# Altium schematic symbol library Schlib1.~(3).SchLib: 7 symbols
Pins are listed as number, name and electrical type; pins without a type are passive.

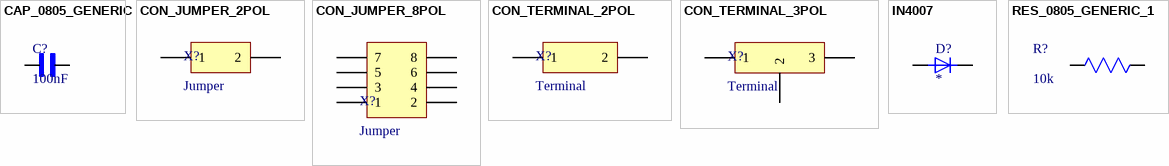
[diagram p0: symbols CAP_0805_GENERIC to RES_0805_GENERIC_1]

## CAP_0805_GENERIC
designator C?, comment 100nF
0.1 ÂµF Â±10% 50V Ceramic Capacitor X7R 0805 (2012 Metric); MF: Samsung Electro-Mechanics; MP: CL21B104KBCNNNC
footprint CAPC2012X95N
pins: 1, 2

## CON_JUMPER_2POL
designator X?, comment Jumper
Manufacturer_Name: Yageo; Manufacturer_Part_Number: RC0805FR-0710KL; Value: 10k
footprint CON_JUMPER_2POL (Jumper)
pins: 1, 2

## CON_JUMPER_8POL
designator X?, comment Jumper
Manufacturer_Name: Yageo; Manufacturer_Part_Number: RC0805FR-0710KL; Value: 10k
footprint CON_JUMPER_8POL (Jumper)
pins: 1, 2, 3, 4, 5, 6, 7, 8

## CON_TERMINAL_2POL
designator X?, comment Terminal
Terminal Screw; Manufacturer_Name: Yageo; Manufacturer_Part_Number: RC0805FR-0710KL; Value: 10k
footprint CON_TERMINAL_2POL (Terminal Screw)
pins: 1, 2

## CON_TERMINAL_3POL
designator X?, comment Terminal
Terminal block; Manufacturer_Name: Yageo; Manufacturer_Part_Number: RC0805FR-0710KL; Value: 10k
footprint CON_TERMINAL_3POL (Terminal Screw)
pins: 1, 2, 3

## IN4007
designator D?
Diode Standard 1000 V 1A Through Hole DO-204AL (DO-41); MF: Vishay Semiconductor; MP: IN4007
footprint DIOAD1070W78L470D235P
pins: A, C

## RES_0805_GENERIC_1
designator R?, comment 10k
Description; Manufacturer_Name: Yageo; Manufacturer_Part_Number: RC0805FR-0710KL
footprint RC0805N_YAG-M
pins: 1, 2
